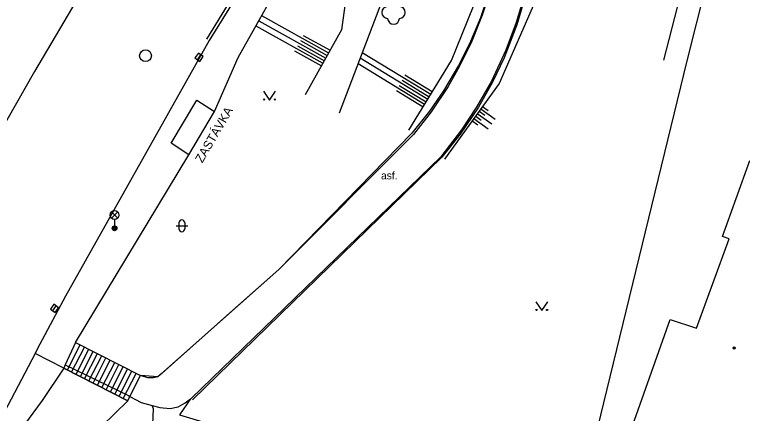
# Model space of a CAD drawing. Extents: x -599951 to -598963, y -1164095 to -1162939.
# Drawn here: x -599064.1 to -599002.4, y -1163454.9 to -1163421.1 of the extents above; entities that cross this region are included whole.
import ezdxf

# ---------------------------------------------------------------- set-up
doc = ezdxf.new("R2010")
doc.units = 0
for name, color, linetype in [('Level 10', 7, 'Continuous'), ('Level 11', 7, 'Continuous'), ('Level 14', 7, 'Continuous'), ('Level 15', 7, 'Continuous'), ('Level 22', 7, 'Continuous'), ('Level 27', 7, 'Continuous'), ('Level 33', 7, 'Continuous'), ('Level 36', 7, 'Continuous'), ('Level 39', 7, 'Continuous'), ('Level 40', 7, 'Continuous'), ('Level 41', 7, 'Continuous'), ('Level 52', 7, 'Continuous'), ('Level 9', 7, 'Continuous')]:
    doc.layers.add(name, color=color, linetype=linetype)

msp = doc.modelspace()

# ---------------------------------------------------------------- linework, layer by layer
at = {"layer": 'Level 10'}
for points in [[(-599047.86, -1163401.99), (-599050.23, -1163405.73), (-599057.47, -1163417.43), (-599062.46, -1163425.89), (-599072.58, -1163443.64), (-599087.83, -1163474.25), (-599089.79, -1163478.58), (-599092.69, -1163484.97), (-599097.7, -1163496.33)], [(-599042.63, -1163415.16), (-599047.62, -1163423.27), (-599059.83, -1163444.92), (-599062.215, -1163449.439), (-599062.4, -1163449.79)], [(-599062.4, -1163449.79), (-599069.1, -1163462.48), (-599076.43, -1163477.22), (-599079.26, -1163483.24), (-599083.36, -1163492.14)]]:
    msp.add_lwpolyline(points, dxfattribs=at)
at = {"layer": 'Level 11'}
for points in [[(-599047.82, -1163423.14), (-599042.84, -1163415), (-599041.02, -1163412.14), (-599038.36, -1163407.95)], [(-599003.87, -1163412.18), (-599007.09, -1163424.98), (-599016.08, -1163461.76), (-598985.22, -1163472.29)], [(-599020.89, -1163419.36), (-599021.59, -1163421.72), (-599022.47, -1163424.07), (-599023.69, -1163426.71), (-599024.91, -1163428.86), (-599026.21, -1163430.82), (-599027.97, -1163433.11), (-599049.15, -1163453.6)], [(-599023.76, -1163418.94), (-599024.46, -1163421.11), (-599025.35, -1163423.32), (-599026.38, -1163425.43), (-599027.35, -1163427.15), (-599028.79, -1163429.31), (-599030.29, -1163431.24)], [(-599047.18, -1163429.27), (-599045.18, -1163424.7)], [(-599049.37, -1163432.94), (-599050.85, -1163431.96), (-599048.67, -1163428.32), (-599047.18, -1163429.27)], [(-599049.37, -1163432.94), (-599047.18, -1163429.27)], [(-599030.29, -1163431.24), (-599041.73, -1163442.66), (-599045.888, -1163446.348), (-599051.62, -1163451.453), (-599051.782, -1163451.602), (-599051.99, -1163451.76), (-599052.343, -1163451.845), (-599052.84, -1163451.845), (-599053.45, -1163451.67)], [(-599058.97, -1163448.86), (-599049.37, -1163432.94)], [(-599058.97, -1163448.86), (-599059.844, -1163450.757), (-599059.97, -1163451.03)], [(-599059.66, -1163451.19), (-599058.58, -1163449.06)], [(-599058.97, -1163448.86), (-599053.45, -1163451.67)], [(-599059.3, -1163451.37), (-599058.21, -1163449.25)], [(-599058.93, -1163451.56), (-599057.85, -1163449.43)], [(-599058.56, -1163451.75), (-599057.48, -1163449.62)], [(-599059.97, -1163451.03), (-599062.4, -1163449.79)], [(-599058.2, -1163451.93), (-599057.12, -1163449.8)], [(-599057.84, -1163452.11), (-599056.75, -1163449.99)], [(-599057.47, -1163452.3), (-599056.39, -1163450.17)], [(-599059.84, -1163450.76), (-599054.49, -1163453.36), (-599054.35, -1163453.43), (-599053.4, -1163453.96), (-599052.48, -1163454.2), (-599051.83, -1163454.37), (-599050.94, -1163454.45), (-599050.26, -1163454.32), (-599049.67, -1163453.99), (-599049.21, -1163453.65), (-599049.15, -1163453.6)], [(-599057.1, -1163452.49), (-599056.02, -1163450.36)], [(-599056.74, -1163452.68), (-599055.65, -1163450.55)], [(-599056.37, -1163452.87), (-599055.29, -1163450.73)], [(-599056.01, -1163453.05), (-599054.92, -1163450.92)], [(-599054.54, -1163453.8), (-599059.97, -1163451.03)], [(-599055.64, -1163453.24), (-599054.56, -1163451.11)], [(-599055.28, -1163453.42), (-599054.19, -1163451.3)], [(-599054.92, -1163453.61), (-599053.83, -1163451.48)], [(-599054.54, -1163453.8), (-599054.352, -1163453.433), (-599053.45, -1163451.67)], [(-599049.21, -1163453.65), (-599050.15, -1163455), (-599037.96, -1163458.64)], [(-599053.12, -1163457.43), (-599052.42, -1163455.78), (-599052.37, -1163454.49), (-599052.48, -1163454.2)]]:
    msp.add_lwpolyline(points, dxfattribs=at)
at = {"layer": 'Level 14'}
for points in [[(-599033.46, -1163413.42), (-599035.74, -1163417.61), (-599036.41, -1163422.36), (-599039.48, -1163427.87)], [(-599033.46, -1163413.42), (-599031.74, -1163416.65), (-599036.6, -1163429.41)], [(-599020.18, -1163414.61), (-599019.82, -1163419.57), (-599023.04, -1163426.9), (-599027.66, -1163433.33)], [(-599045.18, -1163424.7), (-599040.57, -1163416.48)], [(-599030.69, -1163430.85), (-599027.08, -1163424.94), (-599024.71, -1163419.14), (-599024.3, -1163416.86)], [(-599006.99, -1163416.79), (-599009.07, -1163424.91)], [(-599059.97, -1163451.03), (-599061.8, -1163453.78), (-599063.29, -1163455.82), (-599071.2, -1163471.22)], [(-599054.54, -1163453.8), (-599057.85, -1163457.03)]]:
    msp.add_lwpolyline(points, dxfattribs=at)
at = {"layer": 'Level 15'}
for points in [[(-599043.19, -1163421.14), (-599037.5, -1163424.31)], [(-599043.43, -1163421.58), (-599037.74, -1163424.75)], [(-599043.67, -1163422.01), (-599037.98, -1163425.19)], [(-599039.65, -1163422.83), (-599037.38, -1163424.09)], [(-599040.14, -1163423.7), (-599037.86, -1163424.97)], [(-599039.89, -1163423.26), (-599037.62, -1163424.53)], [(-599040.38, -1163424.14), (-599038.11, -1163425.4)], [(-599034.64, -1163424.26), (-599028.83, -1163427.81)], [(-599034.82, -1163424.74), (-599029.09, -1163428.23)], [(-599035, -1163425.21), (-599029.35, -1163428.66)], [(-599031.04, -1163426.17), (-599028.7, -1163427.59)], [(-599031.27, -1163426.61), (-599028.96, -1163428.02)], [(-599031.5, -1163427.06), (-599029.22, -1163428.45)], [(-599031.73, -1163427.5), (-599029.48, -1163428.87)], [(-599024.73, -1163429.25), (-599024.24, -1163429.6)], [(-599024.58, -1163429.05), (-599023.37, -1163429.93)], [(-599024.44, -1163428.85), (-599023.95, -1163429.2)], [(-599025.17, -1163429.86), (-599023.95, -1163430.74)], [(-599025.02, -1163429.66), (-599024.54, -1163430.01)], [(-599024.88, -1163429.46), (-599023.66, -1163430.33)], [(-599025.31, -1163430.07), (-599024.83, -1163430.42)]]:
    msp.add_lwpolyline(points, dxfattribs=at)
at = {"layer": 'Level 22'}
for centre, start, end in [((-599032.49, -1163420.88), 90, 270), ((-599031.49, -1163420.88), 270, 90), ((-599031.99, -1163421.38), 180, 0)]:
    msp.add_arc(centre, 0.5, start, end, dxfattribs=at)
at = {"layer": 'Level 27'}
for p, q in [((-599048.635, -1163424.884), (-599048.345, -1163424.476)), ((-599060.905, -1163446.174), (-599060.615, -1163445.766))]:
    msp.add_line(p, q, dxfattribs=at)
for points in [[(-599048.431, -1163425.029), (-599048.141, -1163424.621), (-599048.549, -1163424.331), (-599048.839, -1163424.739)], [(-599060.701, -1163446.319), (-599060.411, -1163445.911), (-599060.819, -1163445.621), (-599061.109, -1163446.029)]]:
    msp.add_lwpolyline(points, close=True, dxfattribs=at)
msp.add_circle((-599053.03, -1163424.55), 0.5, dxfattribs=at)
at = {"layer": 'Level 33'}
for p, q in [((-599055.925, -1163438.32), (-599055.395, -1163437.79)), ((-599055.925, -1163437.79), (-599055.395, -1163438.32)), ((-599055.66, -1163438.43), (-599055.66, -1163439.18))]:
    msp.add_line(p, q, dxfattribs=at)
for centre, radius in [((-599055.66, -1163438.055), 0.375), ((-599055.66, -1163439.18), 0.2), ((-599055.66, -1163439.18), 0.145), ((-599055.66, -1163439.18), 0.0876)]:
    msp.add_circle(centre, radius, dxfattribs=at)
at = {"layer": 'Level 36'}
for p, q in [((-599050.446, -1163438.966), (-599049.446, -1163438.966)), ((-599050.196, -1163438.716), (-599050.196, -1163439.216)), ((-599049.696, -1163438.716), (-599049.696, -1163439.216))]:
    msp.add_line(p, q, dxfattribs=at)
for points in [[(-599043.01, -1163427.56), (-599042.51, -1163428.31), (-599042.01, -1163427.56)], [(-599019.91, -1163445.4), (-599019.41, -1163446.15), (-599018.91, -1163445.4)]]:
    msp.add_lwpolyline(points, dxfattribs=at)
for centre in [(-599042.96, -1163428.26), (-599042.061, -1163428.26), (-599019.86, -1163446.1), (-599018.961, -1163446.1)]:
    msp.add_circle(centre, 0.05, dxfattribs=at)
for centre, start, end in [((-599049.946, -1163438.716), 0, 180), ((-599049.946, -1163439.216), 180, 0)]:
    msp.add_arc(centre, 0.25, start, end, dxfattribs=at)
at = {"layer": 'Level 39'}
for radius in [0.09, 0.0398]:
    msp.add_circle((-599003.09, -1163449.33), radius, dxfattribs=at)
at = {"layer": 'Level 52'}
for points in [[(-599004.07, -1163439.88), (-599001.77, -1163433.43)], [(-599006.29, -1163447.66), (-599003.51, -1163440.08)], [(-599003.51, -1163440.08), (-599004.07, -1163439.88)], [(-599012.83, -1163459.03), (-599008.52, -1163446.91)], [(-599008.52, -1163446.91), (-599006.29, -1163447.66)]]:
    msp.add_lwpolyline(points, dxfattribs=at)
at = {"layer": 'Level 9'}
for points in [[(-599020.12, -1163414.61), (-599020.83, -1163416.89), (-599020.78, -1163419.41), (-599021.52, -1163421.92), (-599022.59, -1163424.72), (-599023.58, -1163426.78), (-599024.78, -1163428.9), (-599026.33, -1163431.2), (-599027.89, -1163433.16)], [(-599024.04, -1163416.86), (-599023.89, -1163419.19), (-599024.61, -1163421.33), (-599025.45, -1163423.34), (-599026.47, -1163425.37), (-599027.74, -1163427.52), (-599028.95, -1163429.26), (-599030.45, -1163431.12)], [(-599030.45, -1163431.12), (-599041.73, -1163442.66), (-599051.99, -1163451.76), (-599053.45, -1163451.67)], [(-599027.89, -1163433.16), (-599049.05, -1163453.73)], [(-599058.97, -1163448.86), (-599053.45, -1163451.67)], [(-599059.97, -1163451.03), (-599054.54, -1163453.8)]]:
    msp.add_lwpolyline(points, dxfattribs=at)

# ---------------------------------------------------------------- texts
at = {"layer": 'Level 40'}
msp.add_text('asf.', height=0.65, dxfattribs=at).set_placement((-599033.05, -1163435.03))
at = {"layer": 'Level 41'}
msp.add_text('ZASTÁVKA', height=0.75, rotation=59.75, dxfattribs=at).set_placement((-599048.22, -1163433.69))

doc.saveas('drawing.dxf')
